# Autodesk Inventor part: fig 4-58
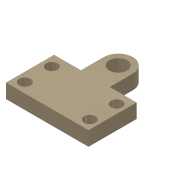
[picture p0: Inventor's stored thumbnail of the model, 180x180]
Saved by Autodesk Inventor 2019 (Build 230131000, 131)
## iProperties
Created: 2004-05
Part Number: fig 4-58
Document SubType Name: Modeling
Designer: CADCIM Technologies
Manufacturer: Standard
Standards Organization: Custom
Density: 1 g/cm^3
Material: Generic
Appearance: Metal-Titanium (Polished)
Author: CADCIM Technologies
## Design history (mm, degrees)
sketch "Sketch1"
  geometry: L1 (39.729, 55.62)-(39.729, 42.054); L2 (39.729, 42.054)-(23.837, 42.054); L3 (23.837, 42.054)-(23.837, 13.516); L4 (23.837, 13.516)-(72.804, 13.516); L5 (72.804, 13.516)-(72.804, 42.054); L6 (72.804, 42.054)-(56.912, 42.054); L7 (56.912, 42.054)-(56.912, 55.62); C1 r 3.354 at (29.212, 35.336); C2 r 3.354 at (29.212, 19.383); C3 r 3.354 at (67.7, 35.336); C4 r 3.354 at (67.7, 19.383); C5 r 5.297 at (48.32, 55.62); A1 r 8.592 centre (48.32, 55.62) between (56.912, 55.62) and (39.729, 55.62)
  constraints: 14 end point, 6 centre point, 4 parallel, 2 equal length, 2 horizontal alignment, 2 point on circle, 2 tangent, 2 vertical alignment, 1 coincident, 1 collinear, 1 perpendicular, 1 vertical
extrude "Extrusion1" new body sketch "Sketch1" distance "d0" = 8.5; taper "d1" = 0 deg
body "Solid1"
